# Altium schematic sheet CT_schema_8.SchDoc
size 277 x 170 mm
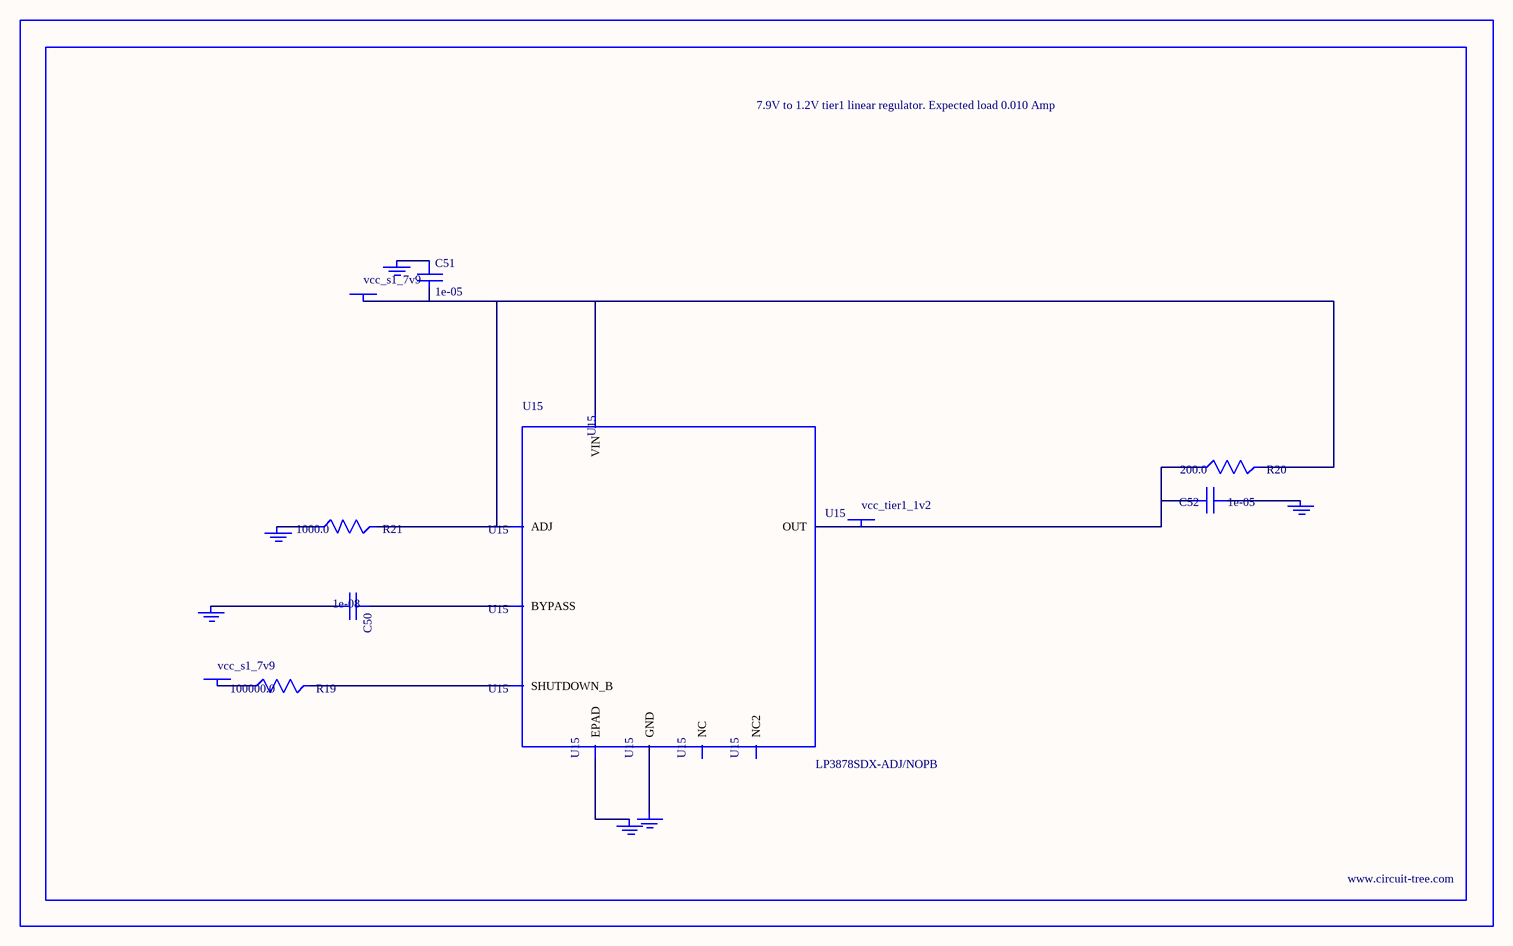
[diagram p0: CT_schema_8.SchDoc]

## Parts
BORDER7  (no value)
C50  1e-08  [C0402]
C51  1e-05  [C1206]
C52  1e-05  [C0805]
GND_INSTANCE_7_0  (no value)
GND_INSTANCE_7_1  (no value)
GND_INSTANCE_7_2  (no value)
GND_INSTANCE_7_3  (no value)
GND_INSTANCE_7_4  (no value)
GND_INSTANCE_7_5  (no value)
POWER_INSTANCE_7_0  vcc_s1_7v9
POWER_INSTANCE_7_1  vcc_s1_7v9
POWER_INSTANCE_7_2  vcc_tier1_1v2
R19  100000.0  [R0603]
R20  200.0  [R0603]
R21  1000.0  [R0603]
U15  LP3878SDX-ADJ/NOPB  [WSON-8]

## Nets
NetC50_1: C50.1 U15.1(BYPASS)
NetC50_2: C50.2 GND_INSTANCE_7_0.0(GND)
NetC51_1: C51.1 GND_INSTANCE_7_1.0(GND)
NetC51_2: C51.2 POWER_INSTANCE_7_0.0(PWR) R20.2 R21.2 U15.4(VIN) U15.6(ADJ)
NetC52_1: C52.1 GND_INSTANCE_7_2.0(GND)
NetC52_2: C52.2 POWER_INSTANCE_7_2.0(PWR) R20.1 U15.5(OUT)
NetGND_INSTANCE_7_3_0: GND_INSTANCE_7_3.0(GND) R21.1
NetGND_INSTANCE_7_4_0: GND_INSTANCE_7_4.0(GND) U15.PAD(EPAD)
NetGND_INSTANCE_7_5_0: GND_INSTANCE_7_5.0(GND) U15.3(GND)
NetPOWER_INSTANCE_7_1_0: POWER_INSTANCE_7_1.0(PWR) R19.1
NetR19_2: R19.2 U15.8(SHUTDOWN_B)

Not connected (* = marked no-connect by the designer): U15 2(NC) 7(NC2)

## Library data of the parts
BORDER7 = BORDER_PAGE7
C50 = C0402C103K3RAC
C51 = C1206C106K3RACTU
C52 = GRM219R60J106ME19D
GND_INSTANCE_7_0-GND_INSTANCE_7_5 = GND
POWER_INSTANCE_7_0-POWER_INSTANCE_7_2 = PWR
R19 = RC0603JR-07100KL
R20 = RC0603JR-07200RL
R21 = RC0603JR-071KL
